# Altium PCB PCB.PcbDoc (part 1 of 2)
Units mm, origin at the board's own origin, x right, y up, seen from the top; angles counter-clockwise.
Board outline 69.72 x 25.78 mm, 2 copper layers (Top Layer, Bottom Layer); 68 components, 49 nets, 251 pads, 101 vias.
Unrouted connection lines stored in the file: 33.
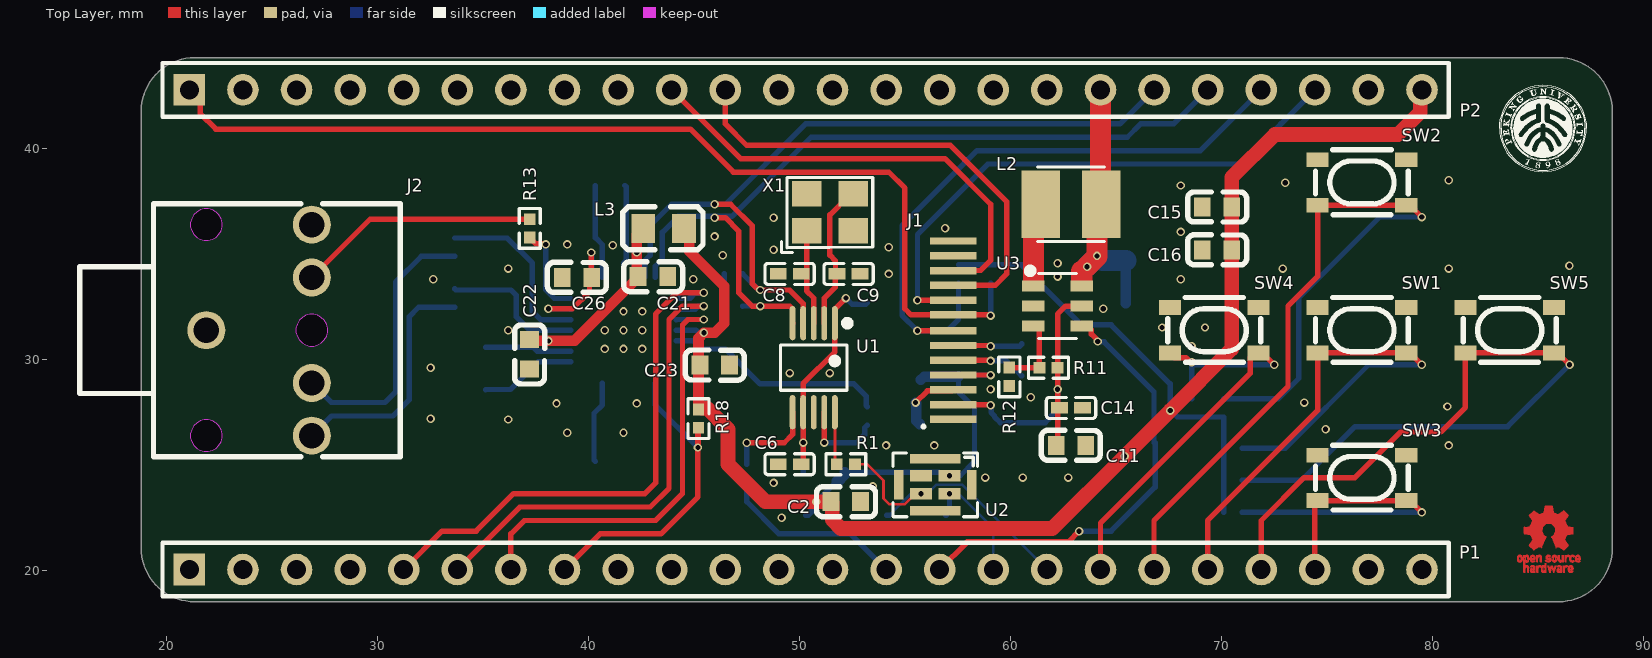
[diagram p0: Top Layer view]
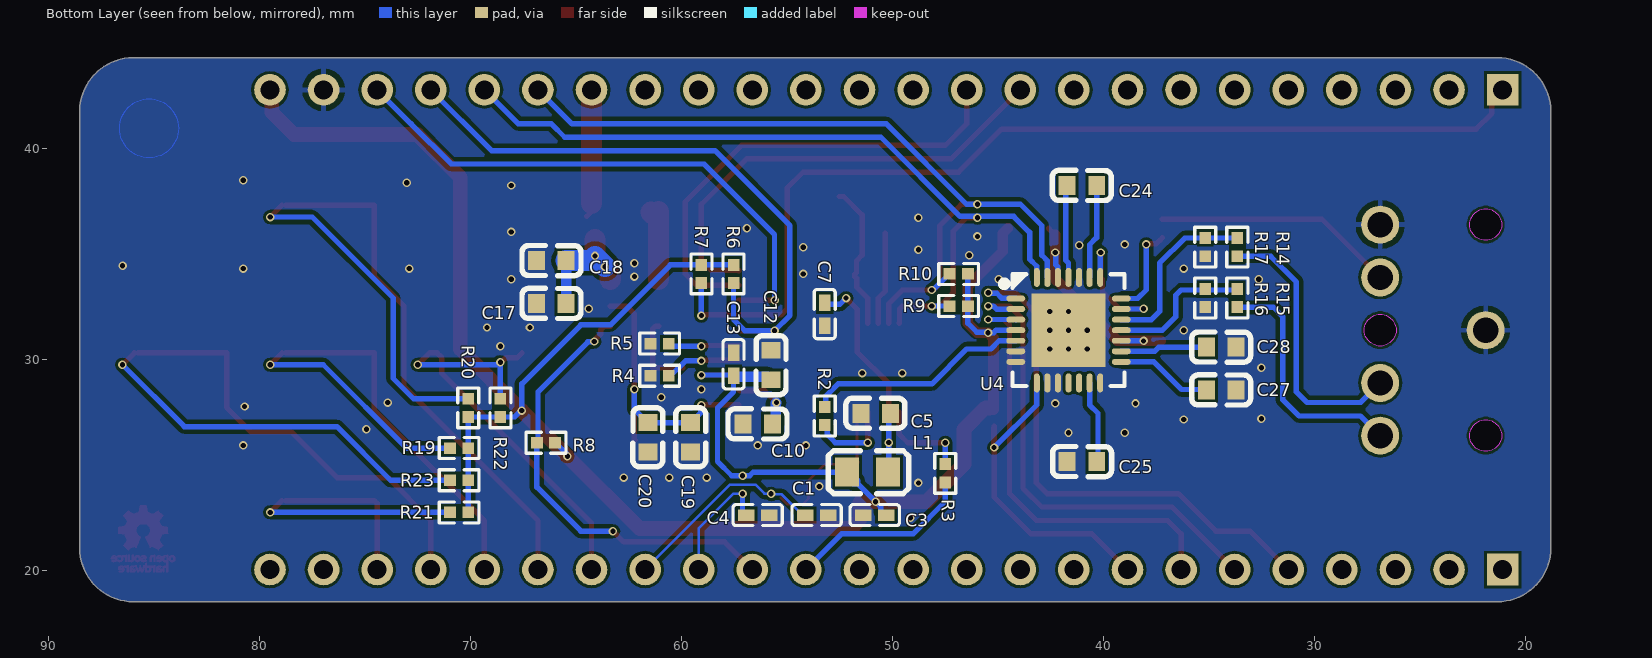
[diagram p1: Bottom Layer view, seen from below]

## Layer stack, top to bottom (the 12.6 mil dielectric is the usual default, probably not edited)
Top Solder: solder mask 0.0102, Solder Resist, Dk 3.5
Top Layer: signal copper 0.035
Dielectric 1: dielectric 0.32, FR-4, Dk 4.8
Bottom Layer: signal copper 0.035
Bottom Solder: solder mask 0.0102, Solder Resist, Dk 3.5

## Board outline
21.336,18.542 cw(c21.336,21.082) 18.796,21.082 18.796,41.783 cw(c21.336,41.783) 21.336,44.323 85.979,44.323 cw(c85.979,41.783) 88.519,41.783 88.519,21.082 cw(c85.979,21.082) 85.979,18.542

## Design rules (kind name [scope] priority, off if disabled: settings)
Clearance [All] p1: gap=0.127 ignorepadtopadclearanceinfootprint=FALSE except(0.2: Arc-Fill Arc-Poly Arc-Region Track-Fill Track-Poly Track-Region)
PolygonConnect [All] p1: thpad.connectstyle=Relief thpad.reliefconductorwidth=0.254 thpad.reliefentries=4 thpad.polygonreliefangle="90 Angle" thpad.airgapwidth=0.254 smdpad.connectstyle=Direct smdpad.reliefconductorwidth=0.254 smdpad.reliefentries=4 smdpad.polygonreliefangle="90 Angle" smdpad.airgapwidth=0.254 via.connectstyle=Direct via.reliefconductorwidth=0.254 via.reliefentries=4 via.polygonreliefangle="90 Angle" via.airgapwidth=0.254
RoutingVias [All] p1: holewidth=0.711 width=1.27 viastyle="Through Hole" minholewidth=0.711 minwidth=1.27 maxholewidth=0.711 maxwidth=1.27
SolderMaskExpansion [All] p1: expansion=0.102 istentingtop=FALSE
Width [All] p1: maxlimit=1 minlimit=0.127 preferedwidth=0.254
30 further rules are at their usual default settings.

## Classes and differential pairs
component class IO: C15 C16 C17 C18 C19 C20 L2 P1 P2 R8 R9 R10 R11 R12 R19 R20 R21 R22 R23 SW1 SW2 SW3 SW4 SW5 U3
component class DAC: C21 C22 C23 C24 C25 C26 C27 C28 J2 L3 R13 R14 R15 R16 R17 R18 U4
component class AUX: C1 C2 C3 C4 C5 C6 C7 C8 C9 C10 C11 C12 C13 C14 J1 L1 R1 R2 R3 R4 R5 R6 R7 U1 U2 X1

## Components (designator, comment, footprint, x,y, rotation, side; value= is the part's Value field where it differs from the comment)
C1 "" C0402 53.594,22.646 r180 bottom value=15pF
C2 "" C0603 52.197,23.281 r180 top value=1uF
C3 "" C0402 50.837,22.646 r180 bottom value=100nF
C4 "" C0402 56.388,22.646 r180 bottom value=100pF
C5 "" C0603 50.8,27.472 r180 bottom value=1uF
C6 "" C0402 49.53,25.059 r0 top value=100nF
C7 "" C0402 53.213,32.171 r90 bottom value=100nF
C8 "" C0402 49.53,34.076 r180 top value=NP
C9 "" C0402 52.324,34.076 r0 top value=NP
C10 "" C0603 56.388,26.964 r180 bottom value=1uF
C11 "" C0603 62.865,25.948 r0 top value=4.7uF
C12 "" C0603 55.753,29.758 r90 bottom value=4.7uF
C13 "" C0402 57.531,29.795 r270 bottom value=100nF
C14 "" C0402 62.865,27.726 r180 top value=100nF
C15 "" C0603 69.785,37.251 r180 top value=10uF
C16 "" C0603 69.785,35.219 r180 top value=10uF
C17 "" C0603 66.167,32.679 r0 bottom value=10uF
C18 "" C0603 66.167,34.711 r0 bottom value=1uF
C19 "" C0603 59.563,26.329 r270 bottom value=1uF
C20 "" C0603 61.595,26.329 r270 bottom value=1uF
C21 "" C0603 43.053,33.949 r180 top value=1uF
C22 "" C0603 37.211,30.266 r90 top value=1uF
C23 "" C0603 45.974,29.758 r180 top value=1uF
C24 "" C0603 41.021,38.267 r180 bottom value=470nF
C25 "" C0603 41.021,25.186 r0 bottom value=1uF
C26 "" C0603 39.455,33.909 r0 top value=2.2uF
C27 "" C0603 34.417,28.575 r180 bottom value=1uF
C28 "" C0603 34.417,30.607 r180 bottom value=1uF
J1 "X077-6428TSWCG01-H13" OLED 57.277,31.409 r0 top
J2 "" AUDIO-TH_PJ-3062-HD-G 24.384,31.409 r0 top
L1 "" L0805 51.181,24.678 r0 bottom value=10uH
L2 "LQH3NPN150MMEL" IND-SMD_L3.0-W3.0_LQH3NPN 62.865,37.378 r180 top value=15uH
L3 "" L0805 43.561,36.235 r0 top value=10uH
P1 "Header 24" HDR1X24 21.082,20.066 r0 top
P2 "Header 24" HDR1X24 21.082,42.799 r0 top
R1 "" R0402 52.197,25.059 r0 top value=20Ω
R2 "" R0402 53.213,27.345 r90 bottom value=20Ω
R3 "" R0402 47.498,24.626 r270 bottom value=20Ω
R4 "4.7k" R0402 61.035,29.25 r0 bottom
R5 "" R0402 61.035,30.774 r180 bottom value=560kΩ
R6 "4.7k" R0402 57.531,34.076 r90 bottom
R7 "4.7k" R0402 59.055,34.076 r90 bottom
R8 "4.7k" R0402 66.421,26.075 r180 bottom
R9 "4.7k" R0402 46.863,32.552 r180 bottom
R10 "4.7k" R0402 46.863,34.076 r180 bottom
R11 "" R0402 61.797,29.631 r0 top value=560kΩ
R12 "" R0402 59.944,29.198 r90 top value=54.2kΩ
R13 "" R0402 37.211,36.235 r90 top value=20Ω
R14 "" R0402 33.655,35.346 r270 bottom value=20Ω
R15 "" R0402 33.655,32.933 r270 bottom value=20Ω
R16 "" R0402 35.179,32.933 r270 bottom
R17 "" R0402 35.179,35.346 r270 bottom
R18 "" R0402 45.212,27.218 r90 top value=8.2kΩ
R19 "4.7k" R0402 70.537,25.821 r0 bottom
R20 "4.7k" R0402 70.104,27.726 r90 bottom
R21 "4.7k" R0402 70.537,22.773 r0 bottom
R22 "4.7k" R0402 68.58,27.726 r90 bottom
R23 "4.7k" R0402 70.537,24.297 r0 bottom
SW1 "PTS810SJM250SMTRLFS" KEY-SMD_4P-L4.2-W3.2-P2.20-LS4.6 76.656,31.409 r180 top
SW2 "PTS810SJM250SMTRLFS" KEY-SMD_4P-L4.2-W3.2-P2.20-LS4.6 76.656,38.409 r180 top
SW3 "PTS810SJM250SMTRLFS" KEY-SMD_4P-L4.2-W3.2-P2.20-LS4.6 76.656,24.409 r180 top
SW4 "PTS810SJM250SMTRLFS" KEY-SMD_4P-L4.2-W3.2-P2.20-LS4.6 69.656,31.409 r180 top
SW5 "PTS810SJM250SMTRLFS" KEY-SMD_4P-L4.2-W3.2-P2.20-LS4.6 83.656,31.409 r180 top
U1 "SI5351A-B-GTR" MSOP-10_L3.0-W3.0-P0.50-LS5.0-BL 50.673,29.631 r180 top
U2 "" MIC-SMD_8P-L3.0-W4.0-P0.85-BL 56.429,24.086 r0 top
U3 "TLV61046ADBVR" SOT-23-6_L2.9-W1.6-P0.95-LS2.8-BL 62.23,32.552 r270 top
U4 "MAX9850ETI+" QFN-28_L5.0-W5.0-P0.50-TL-EP3.5 41.656,31.409 r180 bottom
X1 "" OSC-SMD_4P-L3.2-W2.5-BL 51.435,36.997 r0 top value=24.576MHz

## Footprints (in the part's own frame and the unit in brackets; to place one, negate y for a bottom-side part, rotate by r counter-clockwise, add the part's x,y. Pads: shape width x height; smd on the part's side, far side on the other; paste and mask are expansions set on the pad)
AUDIO-TH_PJ-3062-HD-G [mm]
  round 1.801 hole 1.199 mask+0.051: 1(-2.499,0) 2(2.499,5.001) 3(2.499,2.499) 4(2.499,-2.499) 5(2.499,-4.999)
  Keep-Out Layer board cut-out: 3.249,0 3.249,0.099 3.198,0.289 3.099,0.46 2.959,0.6 2.789,0.698 2.598,0.749 2.401,0.749 2.21,0.698 2.039,0.6 1.9,0.46 1.801,0.289 1.75,0.099 1.75,0 1.75,-0.099 1.801,-0.289 1.9,-0.46 2.039,-0.6 2.21,-0.698 2.401,-0.749 2.598,-0.749 2.789,-0.698 2.959,-0.6 3.099,-0.46 3.198,-0.289 3.249,-0.099 3.249,0 3.249,0
  Keep-Out Layer board cut-out: -1.75,-4.999 -1.75,-4.9 -1.801,-4.71 -1.9,-4.539 -2.039,-4.399 -2.21,-4.3 -2.401,-4.249 -2.598,-4.249 -2.789,-4.3 -2.959,-4.399 -3.099,-4.539 -3.198,-4.71 -3.249,-4.9 -3.249,-4.999 -3.249,-5.097 -3.198,-5.288 -3.099,-5.459 -2.959,-5.598 -2.789,-5.697 -2.598,-5.748 -2.401,-5.748 -2.21,-5.697 -2.039,-5.598 -1.9,-5.459 -1.801,-5.288 -1.75,-5.097 -1.75,-4.999 -1.75,-4.999
  Keep-Out Layer board cut-out: -1.75,5.001 -1.75,5.1 -1.801,5.29 -1.9,5.461 -2.039,5.601 -2.21,5.699 -2.401,5.751 -2.598,5.751 -2.789,5.699 -2.959,5.601 -3.099,5.461 -3.198,5.29 -3.249,5.1 -3.249,5.001 -3.249,4.903 -3.198,4.712 -3.099,4.541 -2.959,4.402 -2.789,4.303 -2.598,4.252 -2.401,4.252 -2.21,4.303 -2.039,4.402 -1.9,4.541 -1.801,4.712 -1.75,4.903 -1.75,5.001 -1.75,5.001
  silkscreen extent -8.5,-6 6.7,6
C0402 [mm]
  rect 0.79x0.54 smd mask+0.051: 1(-0.545,0) 2(0.545,0)
  silkscreen extent -1.17,-0.5 1.17,0.5
C0603 [mm]
  rect 0.8x0.9 smd mask+0.051: 1(-0.7,0) 2(0.7,0)
  silkscreen extent -1.41,-0.71 1.39,0.72
HDR1X24 [mm] "Connector; Header; 24 Position"
  rect 1.5x1.5 hole 0.9: 1(0,0)
  round 1.5 hole 0.9: 2(2.54,0) 3(5.08,0) 4(7.62,0) 5(10.16,0) 6(12.7,0) 7(15.24,0) 8(17.78,0) 9(20.32,0) 10(22.86,0) 11(25.4,0) 12(27.94,0) 13(30.48,0) 14(33.02,0) 15(35.56,0) 16(38.1,0) 17(40.64,0) 18(43.18,0) 19(45.72,0) 20(48.26,0) 21(50.8,0) 22(53.34,0) 23(55.88,0) 24(58.42,0)
  silkscreen extent -1.27,-1.27 59.69,1.27
IND-SMD_L3.0-W3.0_LQH3NPN [mm]
  rect 1.824x3.22 smd paste+0 mask+0.051: 1(1.428,0) 2(-1.428,0)
  silkscreen extent -1.58,-1.76 1.58,1.76
KEY-SMD_4P-L4.2-W3.2-P2.20-LS4.6 [mm]
  rect 1.05x0.7 smd paste+0 mask+0.051: 1(-2.1,1.075) 2(2.1,1.075) 3(-2.1,-1.075) 4(2.1,-1.075)
  silkscreen extent -2.2,-1.55 2.2,1.52
L0805 [mm]
  rect 1.133x1.377 smd mask+0.051: 1(-0.966,0) 2(0.966,0)
  silkscreen extent -1.95,-1.02 1.86,1.02
MIC-SMD_8P-L3.0-W4.0-P0.85-BL [mil]
  rect 41.3x21.7 smd mask+2: 1(26.6,16.7) 2(-26.6,16.7) 3(-26.6,-16.7) 4(26.6,-16.7)
  rect 17.7x55.1 smd mask+2: 5(67.9,0) 7(-67.9,0)
  rect 94.5x17.7 smd mask+2: 6(0,48.2) 8(0,-48.2)
  silkscreen extent -79,-60 79,59
MSOP-10_L3.0-W3.0-P0.50-LS5.0-BL [mm]
  oval 0.28x1.62 smd paste+0 mask+0.051: 1(-1,-2.11) 2(-0.5,-2.11) 3(0,-2.11) 4(0.5,-2.11) 5(1,-2.11) 6(1,2.11) 7(0.5,2.11) 8(0,2.11) 9(-0.5,2.11) 10(-1,2.11)
  silkscreen extent -1.74,-2.26 1.58,1.07
OLED [mm]
  rect 2.2x0.35 smd mask+0.051: 1(0,-4.225) 2(0,-3.525) 3(0,-2.825) 4(0,-2.125) 5(0,-1.425) 6(0,-0.725) 7(0,-0.025) 8(0,0.725) 9(0,1.425) 10(0,2.125) 11(0,2.825) 12(0,3.525) 13(0,4.225)
  silkscreen extent -1.52,-4.7 -1.27,-4.44
OSC-SMD_4P-L3.2-W2.5-BL [mm]
  rect 1.4x1.2 smd mask+0.051: 1(-1.1,-0.875) 2(1.1,-0.875) 3(1.1,0.875) 4(-1.1,0.875)
  silkscreen extent -2.29,-1.9 2.03,1.65
QFN-28_L5.0-W5.0-P0.50-TL-EP3.5 [mm]
  oval 0.9x0.28 smd paste-100 mask+0.051: 1(-2.5,1.501) 2(-2.5,1.001) 3(-2.5,0.501) 4(-2.5,0) 5(-2.5,-0.5) 6(-2.5,-1.001) 7(-2.5,-1.501) 15(2.5,-1.501) 16(2.5,-1.001) 17(2.5,-0.5) 18(2.5,0) 19(2.5,0.501) 20(2.5,1.001) 21(2.5,1.501)
  oval 0.28x0.9 smd paste-100 mask+0.051: 8(-1.501,-2.5) 9(-1.001,-2.5) 10(-0.501,-2.5) 11(0,-2.5) 12(0.5,-2.5) 13(1.001,-2.5) 14(1.501,-2.5) 22(1.501,2.5) 23(1.001,2.5) 24(0.5,2.5) 25(0,2.5) 26(-0.501,2.5) 27(-1.001,2.5) 28(-1.501,2.5)
  rect 3.5x3.5 smd paste-100 mask+0.051: 29(0,0)
  silkscreen extent -3.2,-2.65 2.65,2.65
R0402 [mm]
  rect 0.566x0.54 smd mask+0.051: 1(-0.433,0) 2(0.433,0)
  silkscreen extent -0.94,-0.5 0.94,0.5
SOT-23-6_L2.9-W1.6-P0.95-LS2.8-BL [mm]
  rect 0.532x1.072 smd mask+0.051: 1(-0.95,-1.149) 2(0,-1.149) 3(0.95,-1.149) 4(0.95,1.149) 5(0,1.149) 6(-0.95,1.149)
  silkscreen extent -1.82,-1.45 1.54,0.89

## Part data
C1 C8 C9: library part 0402CG150J500NT, JLCPCB Part Class="Basic Part", LCSC Part Name="15pF ±5% 50V", Manufacturer=FH(风华), Temperature Coefficient=C0G, Tolerance=±5%, Voltage Rated=50V
C2 C5 C10 C18 C19 C20 C21 C22 C23 C24 C25 C26 C27 C28: library part CL05A105KA5NQNC, JLCPCB Part Class="Basic Part", LCSC Part Name="1uF ±10% 25V", Manufacturer=SAMSUNG(三星), Temperature Coefficient=X5R, Tolerance=±10%, Voltage Rated=25V
C3 C6 C7 C13 C14: library part CL05B104KO5NNNC, JLCPCB Part Class="Basic Part", LCSC Part Name="100nF ±10% 16V", Manufacturer=SAMSUNG(三星), Temperature Coefficient=X7R, Tolerance=±10%, Voltage Rated=16V
C4: library part 0402CG101J500NT, JLCPCB Part Class="Basic Part", LCSC Part Name="100pF ±5% 50V", Manufacturer=FH(风华), Temperature Coefficient=C0G, Tolerance=±5%, Voltage Rated=50V
C11 C12: library part CL10A475KO8NNNC, JLCPCB Part Class="Basic Part", LCSC Part Name="4.7uF ±10% 16V", Manufacturer=SAMSUNG(三星), Temperature Coefficient=X5R, Tolerance=±10%, Voltage Rated=16V
C15 C16 C17: library part CL10A106KP8NNNC, JLCPCB Part Class="Basic Part", LCSC Part Name="10uF ±10% 10V", Manufacturer=SAMSUNG(三星), Temperature Coefficient=X5R, Tolerance=±10%, Voltage Rated=10V
J2: library part PJ-3062-HD-G, Current Rating (Max)=500mA, JLCPCB Part Class="Extended Part", LCSC Part Name=3.5mm耳机座, Manufacturer="XKB Connectivity(中国星坤)", Operating Temperature Range=-20~+70, Voltage Rating (Max)=30V, Welding Temperature (Max)=235
L1 L3: library part SLM2012100MIT, DC Resistance (DCR)=550mΩ, JLCPCB Part Class="Extended Part", LCSC Part Name="10uH ±20% 360mA 550mΩ", Manufacturer=Sunltech(韩国顺磁), Rated Current=360mA, Ratings=-, Tolerance=±20%
L2: DC Resistance (DCR)=290mΩ, Frequency - Self Resonant=15MHz, JLCPCB Part Class="Extended Part", LCSC Part Name="15uH ±20% 660mA 290mΩ", Manufacturer=muRata(村田), Q @ Freq=-, Rated Current=620mA, Saturation Current (Isat)=660mA, Tolerance=±20%
P1 P2: "Header, 24-Pin"
R1 R2 R3 R5 R11 R12 R13 R14 R15: library part 0603WAF200JT5E, JLCPCB Part Class="Basic Part", LCSC Part Name="20Ω ±1%", Manufacturer=UNI-ROYAL(厚声), Operating Temperature Range=-55~+155, Overload Voltage (Max)=75V, Power(Watts)=1/10W, Temperature Coefficient=±100ppm/, Tolerance=±1%
R4 R6 R7 R8 R9 R10 R19 R20 R21 R22 R23: library part Res_0603
R16 R17: library part VC040205X150WP, Allowable Voltage (AC)=4V, Allowable Voltage (DC)=5.6V, Clamping Voltage=18V, JLCPCB Part Class="Extended Part", LCSC Part Name="5.6V 175pF", Manufacturer=AVX, Peak Current=20A, Varistor Voltage=-
R18: library part 0402WGF8201TCE, JLCPCB Part Class="Basic Part", LCSC Part Name="8.2kΩ ±1%", Manufacturer=UNI-ROYAL(厚声), Operating Temperature Range=-55~+155, Overload Voltage (Max)=50V, Power(Watts)=1/16W, Temperature Coefficient=±100ppm/, Tolerance=±1%
SW1 SW2 SW3 SW4 SW5: Contact Current=50mA, JLCPCB Part Class="Extended Part", LCSC Part Name="4.2*3.2*2.5mm 立贴 轻触开关", Manufacturer=C&K, Voltage Rating (DC)=16V
U1: JLCPCB Part Class="Extended Part", Manufacturer="SILICON LABS(芯科)"
U2: library part MSM261D4030H1CPM, JLCPCB Part Class="Extended Part", Manufacturer=MEMS(敏芯微)
U3: Input Voltage=1.8V~5.5V, JLCPCB Part Class="Extended Part", LCSC Part Name="升压型 输入1.8V~5.5V 输出3.3V~28V", Manufacturer=TI(德州仪器), Operating Temperature=-40℃~+85℃@(TA), Output Current (Max)=-, Output Voltage=3.3V~28V, Switching Frequency=1.05MHz
U4: JLCPCB Part Class="Extended Part", Manufacturer=MAXIM(美信), Output Power=-
X1: library part X322525MOB4SI, Frequency Stability=±30ppm, Frequency Tolerance=±10ppm, JLCPCB Part Class="Basic Part", LCSC Part Name="25MHz ±10ppm 12pF", Load Capacitance=12pF, Manufacturer=YXC扬兴科技, Operating Temperature=-40~+85

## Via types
v1: diameter 0.4, hole 0.25, Top Layer to Bottom Layer, tented both sides, 100 vias
v2: diameter 0.4/0.4 (per signal layer), hole 0.25, Top Layer to Bottom Layer, tented both sides, 1 vias

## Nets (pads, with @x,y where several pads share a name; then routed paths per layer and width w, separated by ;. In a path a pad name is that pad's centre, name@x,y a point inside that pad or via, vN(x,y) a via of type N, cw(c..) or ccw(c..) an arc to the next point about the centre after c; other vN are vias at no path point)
BTN_1: P1.20 R19.2 SW1.1 SW1.2 | length 27.6
  Top Layer w0.254: P1.20@69.342,20.066 69.342,22.392 74.556,27.606 SW1.2@74.556,30.334 SW1.1@78.756,30.334 ; SW1.1@78.931,30.334 v1@79.479,29.786
  Bottom Layer w0.254: R19.2@70.97,25.821 73.025,25.821 76.976,29.772 v1(79.493,29.772)
BTN_2: P1.19 R20.2 SW2.1 SW2.2 | length 40.6
  Top Layer w0.254: P1.19@66.802,20.066 66.802,22.392 73.152,28.742 73.152,32.552 74.556,33.956 SW2.2@74.556,37.334 SW2.1@78.756,37.334 ; SW2.1@78.931,37.334 v1@79.479,36.786
  Bottom Layer w0.254: R20.2@70.104,28.159 72.696,28.159 73.66,29.123 73.66,32.933 77.499,36.772 v1(79.493,36.772)
BTN_3: P1.22 R21.2 SW3.1 SW3.2 | length 16.8
  Top Layer w0.254: P1.22@74.422,20.066 74.422,23.2 SW3.2@74.556,23.334 SW3.1@78.756,23.334 ; SW3.1@78.931,23.334 v1@79.479,22.786
  Bottom Layer w0.254: R21.2@70.97,22.773 v1(79.493,22.772)
BTN_4: P1.18 R22.2 SW4.1 SW4.2 | length 21.3
  Top Layer w0.254: P1.18@64.262,20.066 64.262,22.265 71.358,29.361 71.358,30.111 71.581,30.334 71.931,30.334 v1@72.479,29.786 ; SW4.2@67.556,30.334 67.779,30.111 68.315,30.111 68.541,29.885 v1(68.58,29.885)
  Bottom Layer w0.254: R22.2@68.58,28.159 v1(68.58,29.885) 68.62,29.885 68.733,29.772 v1(72.493,29.772)
BTN_5: P1.21 R23.2 SW5.1 SW5.2 | length 39.6
  Top Layer w0.254: P1.21@71.882,20.066 71.882,22.392 73.914,24.424 76.327,24.424 78.486,26.583 80.391,26.583 81.556,27.748 SW5.2@81.556,30.334 SW5.1@85.756,30.334 ; SW5.1@85.931,30.334 v1@86.479,29.786
  Bottom Layer w0.254: R23.2@70.97,24.297 73.787,24.297 76.327,26.837 83.558,26.837 v1(86.493,29.772)
DAC_AVDD: C21.2 C22.2 L3.1 U4.17 U4.26 | length 11
  Top Layer w0.254: C22.2@37.211,30.966 C22.2@37.276,30.901 ; C21.2@42.291,34.138 C21.2@42.48,33.949 ; L3.1@42.291,35.931 L3.1@42.595,36.235
  Top Layer w0.5: C22.2@37.276,30.901 v1(38.1,30.901) 39.337,30.901 42.172,33.735 42.189,33.735 42.203,33.749 C21.2@42.234,33.749 ; C21.2@42.291,34.138 v1(42.291,35.092) L3.1@42.291,35.931
  Bottom Layer w0.254: v1(38.1,30.901) 38.104,30.905 39.152,30.905 U4.17@39.156,30.909 ; U4.26@42.157,33.909 42.161,33.914 42.161,34.415 42.263,34.517 42.263,35.064 v1(42.291,35.092)
DAC_DATA: P1.7 U4.3 | length 21
  Top Layer w0.254: P1.7@36.322,20.066 36.322,21.757 36.957,22.392 43.18,22.392 44.45,23.662 44.45,31.663 44.704,31.917 v1(45.466,31.917)
  Bottom Layer w0.254: U4.3@44.156,31.91 44.16,31.913 45.462,31.913 v1(45.466,31.917)
DAC_INT: P1.8 R18.1 U4.8 | length 16
  Top Layer w0.254: P1.8@38.862,20.066 40.553,21.757 43.434,21.757 45.184,23.507 v1(45.184,25.849) ; R18.1@45.184,26.865 v1(45.184,25.849) ; R18.1@45.212,26.785 45.198,26.771 45.198,25.863 v1(45.184,25.849)
  Bottom Layer w0.254: U4.8@43.157,28.909 43.157,27.876 v1(45.184,25.849)
DAC_LRCLK: P1.5 U4.1 | length 25.8
  Top Layer w0.254: P1.5@31.242,20.066 33.06,21.884 34.671,21.884 36.449,23.662 42.672,23.662 43.18,24.17 43.18,32.171 44.196,33.187 v1(45.466,33.187)
  Bottom Layer w0.254: U4.1@44.156,32.91 44.161,32.915 44.813,32.915 45.057,33.159 45.438,33.159 v1(45.466,33.187)
DAC_MCLK: R2.2 U4.5 | length 10.6
  Bottom Layer w0.254: U4.5@44.156,30.909 44.951,30.909 45.339,30.52 46.482,30.52 48.133,28.869 52.578,28.869 53.154,28.293 53.154,27.837 R2.2@53.213,27.778
DAC_SCLK: P1.6 U4.2 | length 22.9
  Top Layer w0.254: P1.6@33.782,20.066 36.743,23.027 42.926,23.027 43.815,23.916 43.815,31.917 44.45,32.552 v1(45.466,32.552)
  Bottom Layer w0.254: U4.2@44.156,32.41 45.07,32.41 45.212,32.552 v1(45.466,32.552)
DMIC_CLK: C1.1 P1.17 R1.2 U2.3 | length 13.9
  Top Layer w0.127: R1.2@52.63,25.059 53.192,25.059 53.975,24.276 53.975,23.436 54.257,23.154 54.983,23.154 U2.3@55.3,23.471
  Bottom Layer w0.127: C1.1@54.264,22.646 55.252,23.634 v1@55.725,23.634 ; v1(55.753,23.662) 56.071,23.662 56.494,24.086 57.702,24.086 P1.17@61.722,20.066
  Bottom Layer w0.254: C1.1@54.139,22.646 C1.1@54.264,22.646 ; v1@55.725,23.634 v1(55.753,23.662)
DMIC_DATA: C4.1 P1.16 U2.4 | length 5.8
  Bottom Layer w0.127: v1(57.104,23.662) 57.531,23.662 59.182,22.011 P1.16@59.182,20.066
  Bottom Layer w0.254: C4.1@56.933,22.646 56.961,22.646 57.104,22.789 v1(57.104,23.662)
FPGA_REFCLK: P1.14 R3.2 | length 8.8
  Bottom Layer w0.254: R3.2@47.498,24.193 47.498,23.281 49.022,21.757 52.411,21.757 P1.14@54.102,20.066
GND: C1.2 C2.1 C3.1 C4.2 C5.1 C6.1 C7.1 C8.2 C9.2 C10.1 C11.2 C12.2 C13.1 C14.1 C15.2 C16.2 C17.2 C18.2 C19.2 C20.2 C21.1 C22.1 C23.1 C25.2 C26.1 C27.2 C28.2 J1.12 J2.1 J2.2 P2.23 R4.2 R5.1 R12.1 R16.2 R17.2 SW1.3 SW1.4 SW2.3 SW2.4 SW3.3 SW3.4 SW4.3 SW4.4 SW5.3 SW5.4 U1.8 U2.5 U2.6 U2.7 U2.8 U3.2 U4.6 U4.7 U4.9 U4.10 U4.14 U4.24 U4.29 X1.2 X1.4
  other v1: 49.149,22.519 53.467,24.003 48.768,24.17 58.801,24.424 60.579,24.424 62.738,24.424 54.102,25.948 56.388,25.948 80.772,25.948 38.989,26.543 41.656,26.543 74.93,26.71 36.195,27.178 32.512,27.218 80.705,27.793 38.481,27.94 42.291,27.94 73.914,27.98 60.96,28.234 59.055,28.615 49.53,29.377 51.435,29.377 32.512,29.631 40.767,30.52 41.656,30.52 42.545,30.52 68.58,30.647 36.195,31.409 40.767,31.409 41.656,31.409 42.545,31.409 67.183,31.536 69.215,31.536 41.656,32.298 42.545,32.298 64.389,32.425 32.639,33.822 44.958,33.822 68.072,33.822 62.23,33.949 54.229,34.076 36.195,34.33 72.898,34.33 80.772,34.33 86.487,34.457 62.23,34.584 46.355,34.965 48.768,35.219 41.148,35.433 38.989,35.473 45.974,35.854 68.072,36.068 56.896,36.235 48.768,36.743 68.072,38.267 73.025,38.394 80.772,38.521
  other v2: 54.229,35.346
HP_DT: R13.1 U4.21 | length 4.4
  Top Layer w0.254: R13.1@37.211,35.802 37.211,35.789 37.354,35.646 37.367,35.646 37.512,35.501 37.945,35.501 v1(37.973,35.473)
  Bottom Layer w0.254: v1(37.973,35.473) 37.973,33.314 38.377,32.91 U4.21@39.156,32.91
HP_L: R14.1 R17.1 U4.19 | length 8.4
  Bottom Layer w0.254: R14.1@33.655,35.779 R17.1@35.179,35.779 36.143,35.779 37.338,34.584 37.338,32.298 37.727,31.91 U4.19@39.156,31.91
HP_R: R15.1 R16.1 U4.18 | length 6.9
  Bottom Layer w0.254: R15.1@33.655,33.366 33.707,33.314 35.179,33.314 36.322,33.314 36.576,33.06 36.576,32.044 37.211,31.409 U4.18@39.156,31.409
I2C_SCL: P2.19 R10.1 U1.4 U4.27 | length 39
  Top Layer w0.254: v1(45.974,37.378) 46.736,37.378 47.752,36.362 47.752,33.617 47.982,33.387 48.021,33.387 48.066,33.342 v1@48.066,33.314 ; v1@48.055,33.314 v1@48.066,33.314 ; U1.4@50.173,31.741 50.168,31.746 50.168,32.676 49.53,33.314 v1(48.133,33.314) v1@48.066,33.314
  Bottom Layer w0.254: U4.27@42.657,33.909 42.657,34.696 42.926,34.965 42.926,36.362 43.942,37.378 v1(45.974,37.378) 46.482,37.378 50.292,41.188 65.191,41.188 P2.19@66.802,42.799 ; R10.1@47.296,34.076 47.309,34.076 48.071,33.314 v1(48.133,33.314)
I2C_SDA: P2.20 R9.1 U1.5 U4.28 | length 39.6
  Top Layer w0.254: v1(45.974,36.743) 46.482,36.743 47.117,36.108 47.117,33.187 47.752,32.552 49.532,32.552 49.665,32.42 49.665,31.75 U1.5@49.673,31.741
  Bottom Layer w0.254: U4.28@43.157,33.909 43.162,33.914 43.162,34.439 43.498,34.775 43.498,36.045 44.26,36.807 45.974,36.807 46.8,36.807 50.546,40.553 65.532,40.553 66.167,41.188 67.731,41.188 P2.20@69.342,42.799 ; R9.1@47.296,32.552 47.298,32.554 v1@48.133,32.554
  other v1: 48.133,32.552
NetC24_1: C24.1 U4.25 | length 4.4
  Bottom Layer w0.254: U4.25@41.656,33.909 41.656,34.584 41.783,34.711 41.783,38.205 C24.1@41.721,38.267
NetC24_2: C24.2 U4.23 | length 4.5
  Bottom Layer w0.254: C24.2@40.321,38.267 40.321,35.792 40.655,35.458 U4.23@40.655,33.909
NetC25_1: C25.1 U4.13 | length 3.9
  Bottom Layer w0.254: C25.1@40.321,25.186 40.259,25.248 40.259,27.472 40.655,27.868 U4.13@40.655,28.909
NetC26_2: C26.2 U4.20 U4.22 | length 6.4
  Top Layer w0.254: v1(38.1,32.425) 39.243,32.425 40.045,33.227 40.045,33.822 40.132,33.909 v1(40.132,35.092)
  Bottom Layer w0.254: v1(38.1,32.425) 38.11,32.415 39.151,32.415 U4.20@39.156,32.41 ; v1(40.132,35.092) 40.15,35.074 40.15,33.914 U4.22@40.155,33.909
NetC27_1: C27.1 U4.15 | length 4.6
  Bottom Layer w0.254: C27.1@35.117,28.575 35.137,28.595 36.302,28.595 37.615,29.908 U4.15@39.156,29.908
NetC28_1: C28.1 U4.16 | length 4.1
  Bottom Layer w0.254: C28.1@35.117,30.607 37.378,30.607 37.577,30.408 U4.16@39.156,30.408
NetJ1_6: J1.6 R5.2 | length 3.3
  Top Layer w0.254: J1.6@57.277,30.684 v1@59.055,30.684
  Bottom Layer w0.254: v1(59.055,30.653) 60.447,30.653 60.527,30.734 R5.2@60.527,30.774
NetJ2_3: J2.3 R13.2 | length 11.5
  Top Layer w0.254: J2.3@26.883,33.908 29.643,36.668 R13.2@37.211,36.668
NetJ2_4: J2.4 R14.2 | length 13.1
  Bottom Layer w0.254: J2.4@26.883,28.91 27.813,27.98 30.353,27.98 30.861,28.488 30.861,33.695 32.079,34.913 R14.2@33.655,34.913
NetJ2_5: J2.5 R15.2 | length 11.6
  Bottom Layer w0.254: J2.5@26.883,26.41 27.818,27.345 30.734,27.345 31.496,28.107 31.496,32.044 31.952,32.5 R15.2@33.655,32.5
NetL2_1: L2.1 U3.1 | length 3.7
  Top Layer w1: 61.087,33.822 L2.1@61.087,37.028 ; L2.1@61.087,36.647 L2.1@61.437,36.997
NetR1_1: R1.1 U1.10 | length 2.5
  Top Layer w0.127: R1.1@51.678,25.145 U1.10@51.678,27.516
  Top Layer w0.254: U1.10@51.673,27.521 U1.10@51.678,27.516 ; R1.1@51.678,25.145 R1.1@51.764,25.059
NetR2_1: R2.1 U1.9 | length 4
  Top Layer w0.254: v1(51.173,26.083) U1.9@51.173,27.521
  Bottom Layer w0.254: v1(51.173,26.083) 52.713,26.083 53.086,26.456 53.086,26.785 R2.1@53.213,26.912
NetR3_1: R3.1 U1.6 | length 4.4
  Top Layer w0.254: v1(47.499,26.075) 49.276,26.075 49.673,26.472 U1.6@49.673,27.521
  Bottom Layer w0.254: R3.1@47.498,25.059 v1@47.498,26.075
OLED_CK: J1.10 P2.11 | length 22.7
  Top Layer w0.254: P2.11@46.482,42.799 46.482,41.188 47.498,40.172 57.15,40.172 59.817,37.505 59.817,34.076 59.275,33.534 J1.10@57.277,33.534
OLED_CS#: J1.7 P2.21 R6.1 | length 30.5
  Top Layer w0.254: v1(55.589,31.384) J1.7@57.277,31.384
  Bottom Layer w0.254: R6.1@57.531,33.643 57.531,31.917 56.998,31.384 v1(55.589,31.384) 54.864,32.109 54.864,36.362 58.42,39.918 69.001,39.918 P2.21@71.882,42.799
OLED_MO: J1.11 P2.10 | length 22.2
  Top Layer w0.254: P2.10@43.942,42.799 43.942,42.458 44.283,42.458 47.204,39.537 56.896,39.537 59.055,37.378 59.055,34.711 58.581,34.237 57.28,34.237 J1.11@57.277,34.234
OLED_MODE: J1.5 R4.1 | length 3.6
  Top Layer w0.254: J1.5@57.291,29.998 J1.5@57.277,29.984 v1@59.055,29.984
  Bottom Layer w0.254: v1(59.055,29.953) 59.811,29.953 60.514,29.25 R4.1@60.527,29.25
OLED_RES#: J1.8 P2.1 R7.1 | length 47.6
  Top Layer w0.254: P2.1@21.082,42.799 21.59,42.291 21.59,41.681 22.337,40.934 44.831,40.934 46.863,38.902 54.229,38.902 54.991,38.14 54.991,32.425 55.282,32.134 J1.8@57.277,32.134 v1@59.055,32.134
  Bottom Layer w0.254: v1(59.055,32.103) R7.1@59.055,33.643
OLED_RS: J1.9 P2.22 | length 26.5
  Top Layer w0.254: v1(55.589,32.834) J1.9@57.277,32.834
  Bottom Layer w0.254: v1(55.589,32.834) 55.589,35.944 58.928,39.283 70.906,39.283 72.811,41.188 P2.22@74.422,42.799
OLED_VCOMH: C10.2 J1.3 | length 3.1
  Top Layer w0.254: v1(55.499,27.98) 56.055,28.536 57.229,28.536 J1.3@57.277,28.584
  Bottom Layer w0.5: v1(55.499,27.98) 55.538,27.941 55.538,27.114 C10.2@55.688,26.964
OLED_VPP: C11.1 C14.2 C19.1 C20.1 J1.2 R11.2 U3.5 | length 14.1
  Top Layer w0.254: J1.2@57.277,27.884 v1@59.055,27.884 ; C11.1@62.195,26.202 62.214,26.202 62.23,26.218 62.23,27.599 62.23,27.853 v1(62.23,28.615) R11.2@62.23,29.631 62.23,32.171 62.611,32.552 U3.5@63.379,32.552
  Bottom Layer w0.254: v1(59.055,27.853) 59.083,27.825 59.083,27.509 59.24,27.352 59.24,27.302 59.513,27.029 C19.1@59.563,27.029 C20.1@61.595,27.029 61.645,27.029 61.918,27.302 61.918,27.352 62.23,27.664 v1(62.23,28.615)
OLED_VPP_EN: P1.15 R8.1 U3.4 | length 21.2
  Top Layer w0.254: P1.15@56.642,20.066 57.952,21.376 62.738,21.376 v1(63.246,21.884) ; U3.4@63.379,31.602 63.649,31.602 63.827,31.424 63.827,31.22 64.135,30.912 v1(64.135,30.873)
  Bottom Layer w0.254: v1(63.246,21.884) 64.77,21.884 66.854,23.968 R8.1@66.854,26.075 ; v1(64.135,30.873) 64.151,30.857 64.433,30.857 66.802,28.488 R8.1@66.802,26.075
OLED_VPP_FB: R11.1 R12.2 U3.3 | length 3.6
  Top Layer w0.254: R12.2@59.944,29.631 R11.1@61.364,29.631 61.364,31.463 61.225,31.602 U3.3@61.081,31.602
PLL_VDD: C5.2 C6.2 C7.2 L1.1 U1.1 U1.7 | length 12.7
  Top Layer w0.254: C6.2@50.075,25.059 50.173,25.157 v1(50.173,26.083) U1.7@50.173,27.521 50.173,28.877 51.673,30.377 U1.1@51.673,31.741 51.673,32.41 v1(52.197,32.933)
  Bottom Layer w0.254: L1.1@50.173,24.678 v1(50.173,26.083) C5.2@50.173,27.472 ; v1(52.197,32.933) 52.491,32.639 53.136,32.639 C7.2@53.213,32.716
PLL_XTAL_N: C8.1 U1.3 X1.1 | length 4.4
  Top Layer w0.254: X1.1@50.335,35.995 50.335,33.949 50.335,33.271 50.673,32.933 U1.3@50.673,31.741
PLL_XTAL_P: C9.1 U1.2 X1.3 | length 7
  Top Layer w0.254: U1.2@51.173,31.741 51.173,32.925 51.695,33.447 51.695,33.865 51.779,33.949 51.779,34.053 51.702,34.13 51.702,34.699 51.435,34.965 51.435,36.872 52.308,37.745 X1.3@52.535,37.745
VDD3V3: C2.2 C3.2 C12.1 C13.2 C15.1 C16.1 C23.2 J1.4 L1.2 L3.2 P2.24 R6.2 R7.2 R8.2 R9.2 R10.2 R18.2 R19.1 R20.1 R21.1 R22.1 R23.1 U2.1 U4.4 | length 107.8
  Top Layer w0.254: L3.2@44.527,36.235 L3.2@44.527,36.357 ; R18.2@45.212,27.651 45.212,27.638 R18.2@45.355,27.495 ; J1.4@57.277,29.284 v1(59.055,29.284)
  Top Layer w0.5: L3.2@44.527,36.235 44.764,35.998 44.764,35.157 46.43,33.49 46.43,31.738 45.974,31.282 45.466,31.282 45.212,31.028 R18.2@45.212,27.651
  Top Layer w0.7: R18.2@45.466,27.726 45.593,27.726 46.609,26.71 46.609,25.059 48.387,23.281 v1(50.8,23.281) C2.2@51.435,23.281 ; C2.2@51.497,23.281 51.547,23.231 51.547,22.421 51.957,22.011 61.976,22.011 v1(65.405,25.44) v1(67.564,27.599) 70.485,30.52 C16.1@70.485,35.219 C15.1@70.485,37.251 70.485,38.648 72.517,40.68 78.359,40.68 79.417,41.738 79.417,42.714 P2.24@79.502,42.799
  Bottom Layer w0.254: U4.4@44.156,31.409 45.085,31.409 45.208,31.286 v1(45.47,31.286) 45.498,31.314 46.006,31.314 46.43,31.738 R9.2@46.43,32.552 R10.2@46.43,34.076 ; C3.2@50.292,22.646 50.417,22.646 50.56,22.789 50.56,23.041 v1(50.8,23.281) L1.2@51.759,24.24 ; L1.2@52.147,24.678 56.602,24.678 56.77,24.51 57.617,24.51 58.293,25.186 58.293,27.726 57.531,28.488 57.531,29.227 C13.2@57.531,29.25 57.565,29.284 v1(59.055,29.284) ; R6.2@57.531,34.509 R7.2@59.055,34.509 60.527,34.509 63.373,31.663 64.77,31.663 67.564,28.869 v1(67.564,27.599) 67.604,27.599 67.909,27.293 R22.1@68.58,27.293 R20.1@70.104,27.293 R19.1@70.104,25.821 R23.1@70.104,24.297 R21.1@70.104,22.773 ; v1(65.405,25.44) 65.433,25.468 65.433,25.533 65.975,26.075 R8.2@65.988,26.075
  Bottom Layer w0.5: L1.2@51.759,24.24 51.831,24.24 52.147,24.556 L1.2@52.147,24.678 ; C12.1@55.753,29.058 55.902,29.207 57.511,29.207 C13.2@57.531,29.227
  other v1: 57.104,24.51
VDD5V: C17.1 C18.1 L2.2 P2.18 U3.6 | length 11.7
  Top Layer w0.254: U3.6@63.379,33.502 U3.6@63.649,33.502 ; v1(63.627,34.417) v1@63.627,34.437 ; v1@64.099,34.909 v1(64.099,34.929) ; L2.2@64.262,37.028 L2.2@64.482,36.808 ; L2.2@64.262,37.409 L2.2@64.293,37.378
  Top Layer w1: 63.373,33.822 63.373,34.203 ; v1@63.627,34.437 v1@64.099,34.909 ; v1(64.099,34.929) 64.099,35.706 ; L2.2@64.262,37.409 P2.18@64.262,42.799
  Bottom Layer w0.254: v1@64.099,34.909 v1(64.099,34.929)
  Bottom Layer w0.5: C17.1@65.467,32.679 C18.1@65.467,34.711
  Bottom Layer w1: v1@63.627,34.437 v1@64.099,34.909 ; 64.356,34.711 C18.1@65.467,34.711
pads on no net: J1.1 J1.13 P1.1 P1.2 P1.3 P1.4 P1.9 P1.10 P1.11 P1.12 P1.13 P1.23 P1.24 P2.2 P2.3 P2.4 P2.5 P2.6 P2.7 P2.8 P2.9 P2.12 P2.13 P2.14 P2.15 P2.16 P2.17 U2.2 U4.11 U4.12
